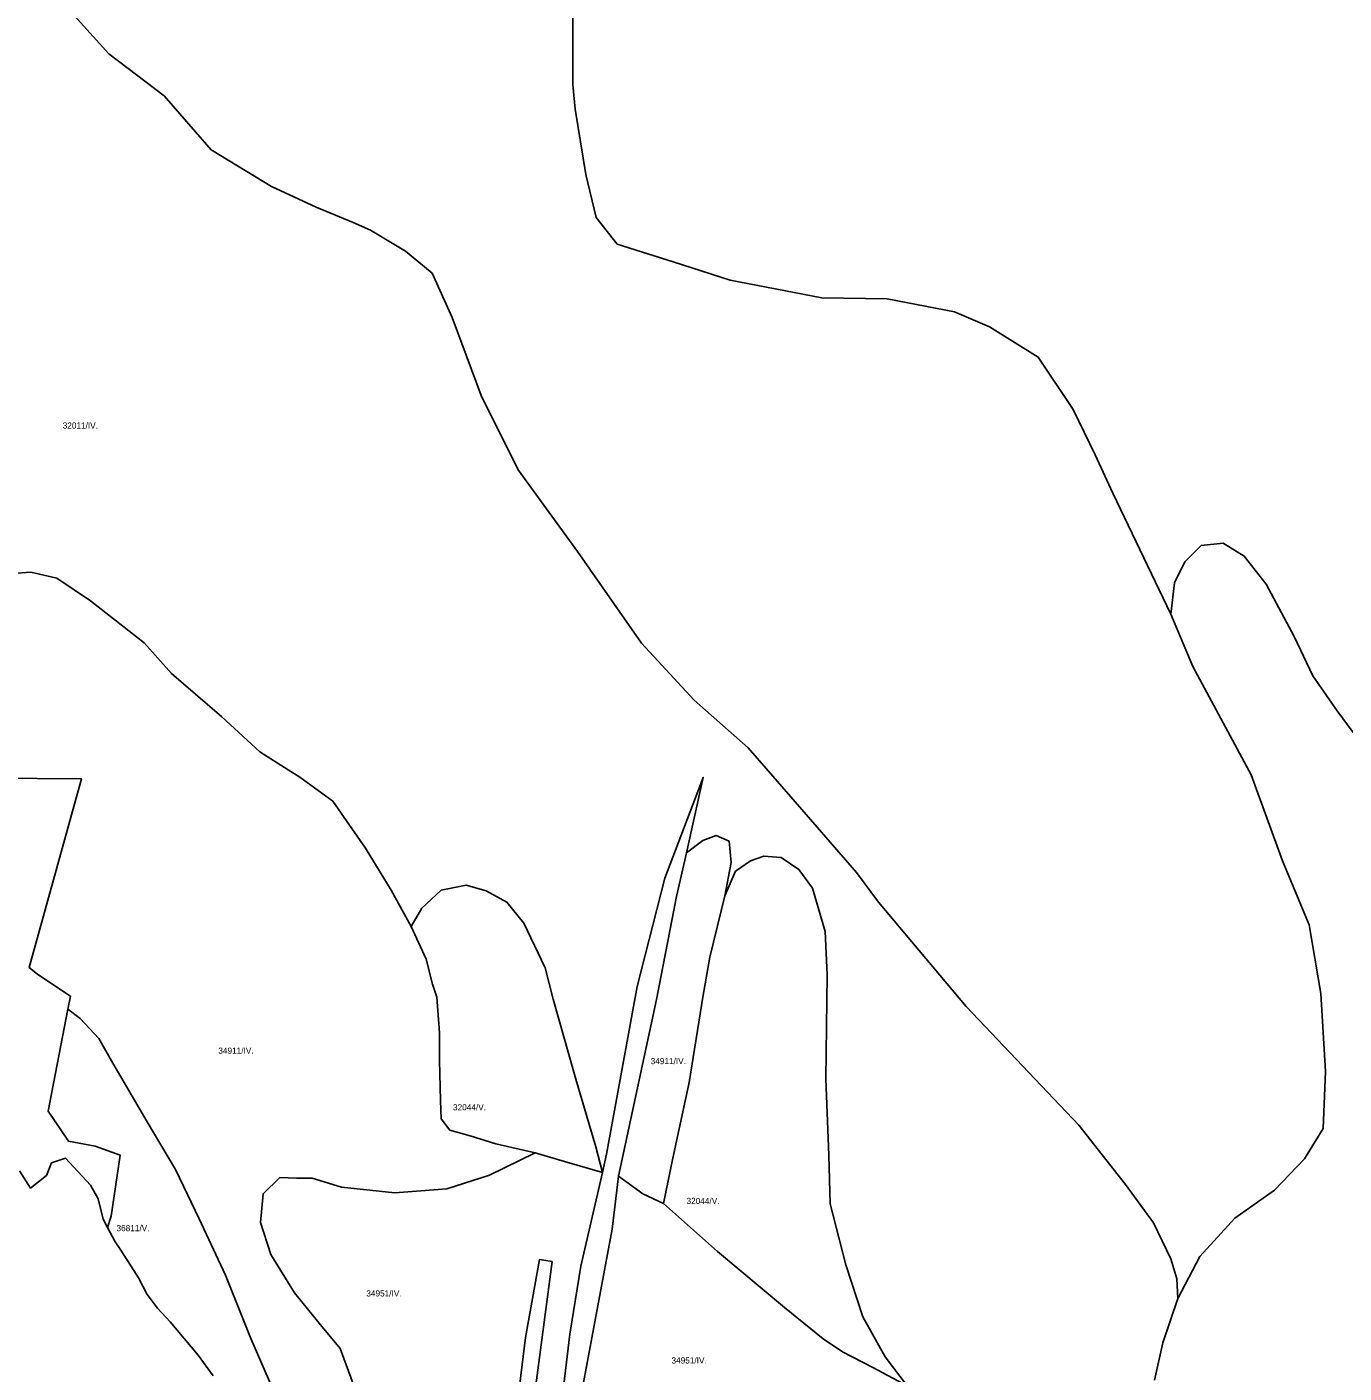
# Model space of a CAD drawing. Extents: x -521621 to -516761, y -1190184 to -1184927.
# Drawn here: x -520857 to -520002, y -1188967 to -1188092 of the extents above; entities that cross this region are included whole.
import ezdxf

# ---------------------------------------------------------------- set-up
doc = ezdxf.new("R2010")
doc.units = 0
doc.layers.add('BPEJ_s', color=7, linetype='Continuous')

msp = doc.modelspace()

# ---------------------------------------------------------------- linework, layer by layer
at = {"layer": 'BPEJ_s'}
for p, q in [((-520502.91, -1188129.57), (-520502.91, -1188081.12)), ((-520501.2, -1188145.65), (-520502.91, -1188129.57)), ((-520494.4, -1188187.98), (-520501.2, -1188145.65)), ((-520487.6, -1188215.95), (-520494.4, -1188187.98)), ((-520474.01, -1188233.33), (-520487.6, -1188215.95)), ((-520437.75, -1188244.67), (-520474.01, -1188233.33)), ((-520400.74, -1188256.76), (-520437.75, -1188244.67)), ((-520341.06, -1188268.1), (-520400.74, -1188256.76)), ((-520298.76, -1188268.85), (-520341.06, -1188268.1)), ((-520254.95, -1188277.17), (-520298.76, -1188268.85)), ((-520232.29, -1188286.99), (-520254.95, -1188277.17)), ((-520200.56, -1188306.65), (-520232.29, -1188286.99)), ((-520177.9, -1188340.66), (-520200.56, -1188306.65)), ((-520163.55, -1188370.14), (-520177.9, -1188340.66)), ((-520152.22, -1188395.08), (-520163.55, -1188370.14)), ((-520114.45, -1188473.69), (-520152.22, -1188395.08)), ((-520094.81, -1188429.09), (-520105.39, -1188439.67)), ((-520080.46, -1188427.58), (-520094.81, -1188429.09)), ((-520066.86, -1188435.89), (-520080.46, -1188427.58)), ((-520052.51, -1188454.03), (-520066.86, -1188435.89)), ((-520105.39, -1188439.67), (-520112.18, -1188453.28)), ((-520112.18, -1188453.28), (-520114.45, -1188473.69)), ((-520034.38, -1188488.05), (-520052.51, -1188454.03)), ((-520022.3, -1188513.74), (-520034.38, -1188488.05)), ((-520006.43, -1188536.42), (-520022.3, -1188513.74)), ((-519996.18, -1188550.48), (-520006.43, -1188536.42))]:
    msp.add_line(p, q, dxfattribs=at)
for points in [[(-520502.91, -1188081.12), (-520502.91, -1188105.01), (-520502.91, -1188129.57), (-520501.2, -1188145.65), (-520494.4, -1188187.98), (-520487.6, -1188215.95), (-520474.01, -1188233.33), (-520437.75, -1188244.67), (-520400.74, -1188256.76), (-520341.06, -1188268.1), (-520298.76, -1188268.85), (-520254.95, -1188277.17), (-520232.29, -1188286.99), (-520200.56, -1188306.65), (-520177.9, -1188340.66), (-520163.55, -1188370.14), (-520152.22, -1188395.08), (-520114.45, -1188473.69), (-520100.1, -1188507.7), (-520062.33, -1188577.99), (-520041.94, -1188633.92), (-520024.56, -1188675.49), (-520017.01, -1188720.09), (-520013.99, -1188770.73), (-520015.5, -1188807.77), (-520027.58, -1188827.42), (-520047.22, -1188847.82), (-520072.91, -1188865.96), (-520095.57, -1188890.91), (-520109.92, -1188918.12), (-520110.68, -1188905.27), (-520114.45, -1188892.42), (-520125.78, -1188868.99), (-520143.91, -1188844.05), (-520174.13, -1188805.5), (-520247.4, -1188728.4), (-520304.42, -1188660.57), (-520318.65, -1188641.45), (-520361.35, -1188592.21), (-520389, -1188560.47), (-520423.98, -1188529.54), (-520458.14, -1188492.51), (-520499.69, -1188432.87), (-520538.21, -1188379.96), (-520562.39, -1188331.59), (-520581.27, -1188280.95), (-520594.11, -1188252.23), (-520611.49, -1188237.86), (-520634.15, -1188224.26), (-520645.51, -1188219.17), (-520669.39, -1188209.21), (-520698.58, -1188195.94), (-520737.71, -1188172.05), (-520768.22, -1188136.87), (-520804.04, -1188109.66), (-520834.55, -1188075.81)], [(-520834.55, -1188075.81), (-520804.04, -1188109.66), (-520768.22, -1188136.87), (-520737.71, -1188172.05), (-520698.58, -1188195.94), (-520669.39, -1188209.21), (-520645.51, -1188219.17), (-520634.15, -1188224.26), (-520611.49, -1188237.86), (-520594.11, -1188252.23), (-520581.27, -1188280.95), (-520562.39, -1188331.59), (-520538.21, -1188379.96), (-520499.69, -1188432.87), (-520458.14, -1188492.51), (-520423.98, -1188529.54), (-520389, -1188560.47), (-520361.35, -1188592.21), (-520318.65, -1188641.45), (-520304.42, -1188660.57), (-520247.4, -1188728.4), (-520174.13, -1188805.5), (-520143.91, -1188844.05), (-520125.78, -1188868.99), (-520114.45, -1188892.42), (-520110.68, -1188905.27), (-520109.92, -1188918.12), (-520119.74, -1188946.84), (-520125.03, -1188971.03)], [(-520125.03, -1188971.03), (-520119.74, -1188946.84), (-520109.92, -1188918.12), (-520095.57, -1188890.91), (-520072.91, -1188865.96), (-520047.22, -1188847.82), (-520027.58, -1188827.42), (-520015.5, -1188807.77), (-520013.99, -1188770.73), (-520017.01, -1188720.09), (-520024.56, -1188675.49), (-520041.94, -1188633.92), (-520062.33, -1188577.99), (-520100.1, -1188507.7), (-520114.45, -1188473.69), (-520112.18, -1188453.28), (-520105.39, -1188439.67), (-520094.81, -1188429.09), (-520080.46, -1188427.58), (-520066.86, -1188435.89), (-520052.51, -1188454.03), (-520034.38, -1188488.05), (-520022.3, -1188513.74), (-520006.43, -1188536.42), (-519996.18, -1188550.48)], [(-520866.76, -1188447.19), (-520854.73, -1188446.42), (-520837.83, -1188450.26), (-520816.07, -1188464.86), (-520781.25, -1188492.27), (-520763.45, -1188512.06), (-520730.74, -1188540.19), (-520705.99, -1188563.13), (-520687.65, -1188574.75), (-520680.18, -1188579.59), (-520658.63, -1188595.06), (-520637.48, -1188625.58), (-520620.81, -1188652.84), (-520607.79, -1188676.44), (-520598.03, -1188697.6), (-520593.97, -1188713.88), (-520591.12, -1188722.43), (-520589.49, -1188745.62), (-520589.49, -1188763.53), (-520588.68, -1188789.57), (-520588.27, -1188801.37), (-520582.58, -1188808.7), (-520569.57, -1188812.36), (-520552.89, -1188817.65), (-520527.23, -1188823.54), (-520556.96, -1188837.99), (-520584.61, -1188846.95), (-520618.37, -1188849.39), (-520652.93, -1188845.73), (-520672.05, -1188840.03), (-520682.21, -1188840.03), (-520692.99, -1188839.61), (-520703.98, -1188850.05), (-520705.62, -1188868.73), (-520699.03, -1188889.61), (-520683.66, -1188914.34), (-520666.64, -1188935.22), (-520654.01, -1188950.6), (-520644.67, -1188975.88)], [(-520285.71, -1188974.72), (-520299.94, -1188956), (-520314.58, -1188929.96), (-520325.56, -1188896.18), (-520335.73, -1188856.71), (-520336.54, -1188824.97), (-520338.58, -1188775.33), (-520337.76, -1188707.78), (-520338.98, -1188679.7), (-520347.12, -1188651.62), (-520356.06, -1188639.41), (-520367.45, -1188631.68), (-520378.84, -1188630.87), (-520387.38, -1188633.72), (-520397.14, -1188640.63), (-520404.05, -1188656.5), (-520399.98, -1188634.94), (-520401.2, -1188621.1), (-520409.75, -1188617.44), (-520418.29, -1188620.7), (-520429.08, -1188628.68), (-520418.09, -1188579.68), (-520442.98, -1188645.01), (-520461.09, -1188715.37), (-520480.92, -1188824.37), (-520483.63, -1188836.17), (-520487.83, -1188819.68), (-520500.84, -1188775.73), (-520515.48, -1188723.65), (-520520.77, -1188703.3), (-520534.59, -1188674.41), (-520545.57, -1188660.57), (-520558.99, -1188653.25), (-520572.01, -1188649.59), (-520588.27, -1188652.84), (-520600.88, -1188664.64), (-520607.79, -1188676.44), (-520620.81, -1188652.84), (-520637.48, -1188625.58), (-520658.63, -1188595.06), (-520680.18, -1188579.59), (-520687.65, -1188574.75), (-520705.99, -1188563.13), (-520730.74, -1188540.19), (-520763.45, -1188512.06), (-520781.25, -1188492.27), (-520816.07, -1188464.86), (-520837.83, -1188450.26), (-520854.73, -1188446.42), (-520866.76, -1188447.19)], [(-520696.18, -1188980.37), (-520711.81, -1188944.14), (-520728.27, -1188902.97), (-520745.55, -1188866.33), (-520760.77, -1188834.22), (-520779.29, -1188803.34), (-520801.61, -1188765.21), (-520810.66, -1188749.15), (-520822.69, -1188736.18), (-520830.7, -1188730.26), (-520829.07, -1188721.82), (-520850.2, -1188707.56), (-520855.9, -1188703.19), (-520821.97, -1188580.54), (-520936.76, -1188579.79)], [(-520936.76, -1188579.79), (-520821.97, -1188580.54), (-520855.9, -1188703.19), (-520850.2, -1188707.56), (-520829.07, -1188721.82), (-520830.7, -1188730.26), (-520843.49, -1188796.35), (-520830.41, -1188815.83), (-520812.96, -1188819.18), (-520796.86, -1188824.89), (-520802.57, -1188864.53), (-520804.93, -1188871.95), (-520807.86, -1188866.5), (-520811.1, -1188853.35), (-520816.13, -1188844.48), (-520832.36, -1188827.01), (-520841.31, -1188829.98), (-520844.65, -1188838.24), (-520854.95, -1188846.39), (-520862.19, -1188835.28)], [(-520510.37, -1188988.44), (-520504.7, -1188941.33), (-520497.61, -1188897.11), (-520483.63, -1188836.17), (-520480.92, -1188824.37), (-520461.09, -1188715.37), (-520442.98, -1188645.01), (-520418.09, -1188579.68), (-520429.08, -1188628.68), (-520435.44, -1188657.02), (-520448.46, -1188723.98), (-520473.24, -1188838.7), (-520477.32, -1188872.97), (-520495.91, -1188972.7)], [(-520736.45, -1188968.35), (-520746.13, -1188954.96), (-520764.32, -1188933.24), (-520772.44, -1188924.47), (-520779.31, -1188915.55), (-520784.91, -1188904.73), (-520790.93, -1188895.15), (-520791.62, -1188894.05), (-520793.72, -1188890.81), (-520796.32, -1188886.8), (-520799.96, -1188881.2), (-520804.93, -1188871.95), (-520802.57, -1188864.53), (-520796.86, -1188824.89), (-520812.96, -1188819.18), (-520830.41, -1188815.83), (-520843.49, -1188796.35), (-520830.7, -1188730.26), (-520822.69, -1188736.18), (-520810.66, -1188749.15), (-520801.61, -1188765.21), (-520779.29, -1188803.34), (-520760.77, -1188834.22), (-520745.55, -1188866.33), (-520728.27, -1188902.97), (-520711.81, -1188944.14), (-520696.18, -1188980.37)], [(-520644.67, -1188975.88), (-520654.01, -1188950.6), (-520666.64, -1188935.22), (-520683.66, -1188914.34), (-520699.03, -1188889.61), (-520705.62, -1188868.73), (-520703.98, -1188850.05), (-520692.99, -1188839.61), (-520682.21, -1188840.03), (-520672.05, -1188840.03), (-520652.93, -1188845.73), (-520618.37, -1188849.39), (-520584.61, -1188846.95), (-520556.96, -1188837.99), (-520527.23, -1188823.54), (-520508.16, -1188829.04), (-520483.63, -1188836.17), (-520497.61, -1188897.11), (-520504.7, -1188941.33), (-520510.37, -1188988.44)], [(-520495.91, -1188972.7), (-520477.32, -1188872.97), (-520473.24, -1188838.7), (-520457.32, -1188850.2), (-520443.9, -1188856.31), (-520408.93, -1188887.64), (-520365.42, -1188923.85), (-520340.2, -1188944.2), (-520327.6, -1188952.75), (-520308.08, -1188962.92), (-520285.71, -1188974.72)], [(-520542.47, -1189092.69), (-520516.33, -1188894.07), (-520524.53, -1188892.81), (-520533.51, -1188943.43), (-520551.79, -1189091.48)]]:
    msp.add_lwpolyline(points, dxfattribs=at)
for points in [[(-520473.24, -1188838.7), (-520448.46, -1188723.98), (-520435.44, -1188657.02), (-520429.08, -1188628.68), (-520418.29, -1188620.7), (-520409.75, -1188617.44), (-520401.2, -1188621.1), (-520399.98, -1188634.94), (-520404.05, -1188656.5), (-520413.81, -1188696.38), (-520418.29, -1188722.43), (-520427.23, -1188777.77), (-520437.8, -1188827.01), (-520443.9, -1188856.31), (-520457.32, -1188850.2)], [(-520443.9, -1188856.31), (-520437.8, -1188827.01), (-520427.23, -1188777.77), (-520418.29, -1188722.43), (-520413.81, -1188696.38), (-520404.05, -1188656.5), (-520397.14, -1188640.63), (-520387.38, -1188633.72), (-520378.84, -1188630.87), (-520367.45, -1188631.68), (-520356.06, -1188639.41), (-520347.12, -1188651.62), (-520338.98, -1188679.7), (-520337.76, -1188707.78), (-520338.58, -1188775.33), (-520336.54, -1188824.97), (-520335.73, -1188856.71), (-520325.56, -1188896.18), (-520314.58, -1188929.96), (-520299.94, -1188956), (-520285.71, -1188974.72), (-520308.08, -1188962.92), (-520327.6, -1188952.75), (-520340.2, -1188944.2), (-520365.42, -1188923.85), (-520408.93, -1188887.64)], [(-520607.79, -1188676.44), (-520600.88, -1188664.64), (-520588.27, -1188652.84), (-520572.01, -1188649.59), (-520558.99, -1188653.25), (-520545.57, -1188660.57), (-520534.59, -1188674.41), (-520520.77, -1188703.3), (-520515.48, -1188723.65), (-520500.84, -1188775.73), (-520487.83, -1188819.68), (-520483.63, -1188836.17), (-520508.16, -1188829.04), (-520527.23, -1188823.54), (-520552.89, -1188817.65), (-520569.57, -1188812.36), (-520582.58, -1188808.7), (-520588.27, -1188801.37), (-520588.68, -1188789.57), (-520589.49, -1188763.53), (-520589.49, -1188745.62), (-520591.12, -1188722.43), (-520593.97, -1188713.88), (-520598.03, -1188697.6)], [(-520551.79, -1189091.48), (-520533.51, -1188943.43), (-520524.53, -1188892.81), (-520516.33, -1188894.07), (-520542.47, -1189092.69)]]:
    msp.add_lwpolyline(points, close=True, dxfattribs=at)

# ---------------------------------------------------------------- texts
for s, p in [('32011/IV.', (-520834.09, -1188353.09)), ('34911/IV.', (-520733.01, -1188759.12)), ('34911/IV.', (-520452.25, -1188765.88)), ('32044/V.', (-520580.62, -1188795.91)), ('32044/V.', (-520428.98, -1188856.71)), ('36811/V.', (-520799.13, -1188874.36)), ('34951/IV.', (-520636.92, -1188916.77)), ('34951/IV.', (-520438.74, -1188960.31))]:
    msp.add_text(s, height=4, dxfattribs=at).set_placement(p)

doc.saveas('drawing.dxf')
